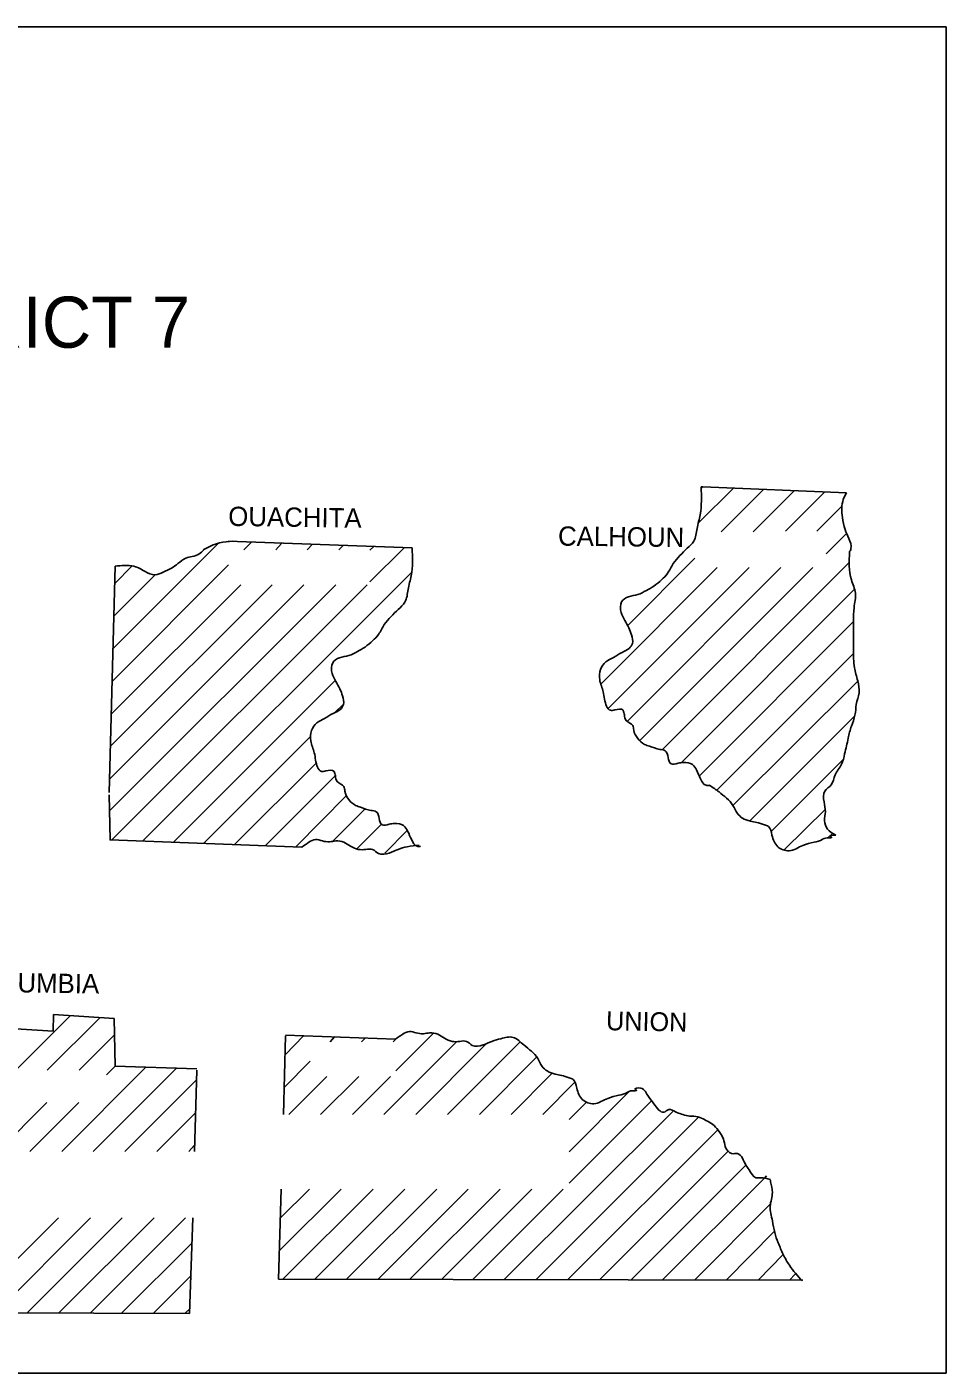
# Model space of a CAD drawing. Extents: x 21307 to 29830, y 1322443 to 1332359.
# Drawn here: x 27579.7 to 27784.6, y 1325697.4 to 1325997.4 of the extents above; entities that cross this region are included whole.
import ezdxf

# ---------------------------------------------------------------- set-up
doc = ezdxf.new("R2010")
doc.units = 0
doc.layers.add('R_Draft', color=7, linetype='Continuous')

msp = doc.modelspace()

# ---------------------------------------------------------------- linework, layer by layer
at = {"layer": 'R_Draft'}
msp.add_lwpolyline([(27384.56, 1325697.42), (27384.56, 1325997.42), (27784.56, 1325997.42), (27784.56, 1325697.42)], close=True, dxfattribs=at)
for points in [[(27729.36, 1325886.92), (27737.16, 1325894.62)], [(27762.36, 1325893.62), (27730.36, 1325894.92), (27729.96, 1325894.92)], [(27729.96, 1325894.52), (27730.36, 1325894.92)], [(27734.46, 1325884.92), (27743.96, 1325894.42)], [(27741.56, 1325884.92), (27750.76, 1325894.12)], [(27748.76, 1325885.02), (27757.56, 1325893.82)], [(27755.76, 1325885.02), (27761.26, 1325890.52)], [(27757.86, 1325880.02), (27762.36, 1325884.52)], [(27598.86, 1325858.82), (27622.46, 1325882.42)], [(27624.56, 1325882.82), (27665.56, 1325881.32)], [(27628.06, 1325880.92), (27629.76, 1325882.62)], [(27635.16, 1325880.92), (27636.46, 1325882.32)], [(27642.16, 1325880.92), (27643.36, 1325882.12)], [(27649.26, 1325880.92), (27650.16, 1325881.82)], [(27656.16, 1325880.82), (27657.06, 1325881.62)], [(27656.16, 1325873.72), (27663.76, 1325881.32)], [(27598.06, 1325826.82), (27599.36, 1325877.22)], [(27598.76, 1325851.62), (27624.66, 1325877.52)], [(27599.26, 1325873.32), (27603.16, 1325877.32)], [(27713.66, 1325864.02), (27728.56, 1325879.02)], [(27721.26, 1325836.32), (27763.06, 1325878.12)], [(27599.06, 1325866.12), (27608.26, 1325875.32)], [(27605.56, 1325816.02), (27665.46, 1325875.92)], [(27707.66, 1325851.02), (27733.56, 1325876.92)], [(27709.36, 1325845.62), (27740.66, 1325876.92)], [(27713.46, 1325842.62), (27747.76, 1325876.92)], [(27716.26, 1325838.32), (27754.86, 1325876.92)], [(27598.16, 1325822.82), (27648.56, 1325873.12)], [(27598.26, 1325829.92), (27641.46, 1325873.12)], [(27598.36, 1325837.12), (27634.36, 1325873.12)], [(27598.56, 1325844.32), (27627.36, 1325873.12)], [(27598.66, 1325816.22), (27655.56, 1325873.12)], [(27725.56, 1325833.52), (27764.06, 1325872.02)], [(27729.66, 1325830.62), (27763.96, 1325864.92)], [(27733.46, 1325827.32), (27763.86, 1325857.72)], [(27612.36, 1325815.72), (27648.46, 1325851.82)], [(27737.06, 1325823.92), (27764.86, 1325851.62)], [(27648.36, 1325844.62), (27650.16, 1325846.42)], [(27740.86, 1325820.52), (27764.26, 1325843.92)], [(27619.16, 1325815.52), (27642.86, 1325839.22)], [(27625.96, 1325815.22), (27644.26, 1325833.42)], [(27745.56, 1325818.12), (27761.46, 1325834.02)], [(27632.86, 1325815.02), (27648.46, 1325830.62)], [(27640.96, 1325814.62), (27598.26, 1325816.22), (27598.06, 1325826.32)], [(27639.66, 1325814.72), (27650.96, 1325826.12)], [(27647.96, 1325816.02), (27655.16, 1325823.22)], [(27748.46, 1325814.02), (27757.66, 1325823.12)], [(27653.26, 1325814.22), (27658.76, 1325819.72)], [(27659.46, 1325813.32), (27664.46, 1325818.32)], [(27758.36, 1325816.82), (27759.16, 1325817.62)], [(27567.56, 1325774.72), (27585.56, 1325773.62), (27585.66, 1325777.32), (27599.16, 1325776.42)], [(27577.26, 1325764.92), (27589.36, 1325777.02)], [(27584.26, 1325764.92), (27595.96, 1325776.62)], [(27599.16, 1325776.42), (27599.36, 1325765.82), (27617.56, 1325765.22)], [(27591.36, 1325764.92), (27599.16, 1325772.72)], [(27636.86, 1325755.04), (27637.36, 1325772.54)], [(27637.26, 1325768.34), (27641.46, 1325772.64)], [(27637.36, 1325772.74), (27661.86, 1325771.84)], [(27647.26, 1325771.24), (27648.36, 1325772.44)], [(27654.26, 1325771.24), (27655.16, 1325772.14)], [(27661.36, 1325771.24), (27662.26, 1325772.14)], [(27661.96, 1325764.74), (27670.36, 1325773.14)], [(27659.26, 1325755.04), (27675.46, 1325771.24)], [(27666.36, 1325755.04), (27682.16, 1325770.84)], [(27673.46, 1325755.04), (27689.56, 1325771.14)], [(27637.06, 1325761.04), (27642.86, 1325766.94)], [(27680.56, 1325755.04), (27693.26, 1325767.84)], [(27587.46, 1325746.82), (27606.16, 1325765.52)], [(27594.46, 1325746.82), (27612.96, 1325765.32)], [(27597.46, 1325763.92), (27599.36, 1325765.82)], [(27617.56, 1325764.92), (27617.06, 1325746.82)], [(27638.06, 1325755.04), (27646.56, 1325763.54)], [(27645.16, 1325755.04), (27653.66, 1325763.54)], [(27652.26, 1325755.04), (27660.76, 1325763.54)], [(27687.66, 1325755.04), (27696.76, 1325764.24)], [(27601.56, 1325746.82), (27617.46, 1325762.72)], [(27694.66, 1325755.04), (27701.86, 1325762.24)], [(27700.56, 1325746.74), (27713.96, 1325760.14)], [(27573.26, 1325746.82), (27584.16, 1325757.72)], [(27580.36, 1325746.82), (27591.26, 1325757.72)], [(27700.56, 1325739.74), (27718.86, 1325758.04)], [(27700.56, 1325753.94), (27704.26, 1325757.64)], [(27608.66, 1325746.82), (27617.26, 1325755.42)], [(27686.16, 1325718.34), (27723.66, 1325755.74)], [(27693.26, 1325718.34), (27729.36, 1325754.44)], [(27700.36, 1325718.34), (27733.66, 1325751.64)], [(27615.76, 1325746.82), (27616.96, 1325748.12)], [(27707.46, 1325718.34), (27735.96, 1325746.84)], [(27714.46, 1325718.24), (27739.96, 1325743.74)], [(27721.46, 1325718.24), (27744.06, 1325740.84), (27744.56, 1325741.34)], [(27635.76, 1325718.34), (27636.36, 1325738.44)], [(27635.96, 1325724.64), (27649.76, 1325738.44)], [(27636.16, 1325731.94), (27642.66, 1325738.44)], [(27636.76, 1325718.34), (27656.86, 1325738.44)], [(27643.86, 1325718.34), (27663.96, 1325738.44)], [(27650.96, 1325718.34), (27671.06, 1325738.44)], [(27657.96, 1325718.34), (27678.06, 1325738.44)], [(27665.06, 1325718.34), (27685.16, 1325738.44)], [(27672.16, 1325718.34), (27692.26, 1325738.44)], [(27679.16, 1325718.34), (27699.26, 1325738.44)], [(27728.46, 1325718.14), (27745.36, 1325735.04)], [(27565.66, 1325710.92), (27586.76, 1325732.02)], [(27572.76, 1325710.92), (27593.86, 1325732.02)], [(27579.76, 1325710.82), (27600.96, 1325732.02)], [(27586.86, 1325710.82), (27608.06, 1325732.02)], [(27593.86, 1325710.82), (27615.06, 1325732.02)], [(27616.66, 1325732.02), (27615.96, 1325710.72)], [(27735.56, 1325718.14), (27746.26, 1325728.94)], [(27600.86, 1325710.82), (27616.36, 1325726.32)], [(27742.66, 1325718.14), (27748.26, 1325723.84)], [(27607.96, 1325710.82), (27616.16, 1325719.02)], [(27752.66, 1325718.14), (27635.76, 1325718.34)], [(27749.66, 1325718.14), (27750.96, 1325719.44)], [(27615.96, 1325710.72), (27551.86, 1325710.92)], [(27615.06, 1325710.82), (27616.06, 1325711.82)]]:
    msp.add_lwpolyline(points, dxfattribs=at)
for points in [[(27729.96, 1325894.92), (27729.76, 1325888.72), (27729.06, 1325885.62), (27728.36, 1325882.82), (27726.86, 1325881.22), (27725.26, 1325879.62), (27723.76, 1325877.82), (27722.46, 1325875.62), (27721.16, 1325874.22), (27719.46, 1325872.82), (27717.76, 1325871.82), (27715.86, 1325870.92), (27713.76, 1325870.42), (27712.26, 1325869.32), (27712.16, 1325866.92), (27713.86, 1325863.52), (27714.46, 1325861.92), (27714.66, 1325860.02), (27713.96, 1325858.92), (27712.36, 1325858.02), (27710.46, 1325856.92), (27708.76, 1325855.92), (27707.56, 1325854.22), (27707.36, 1325851.92), (27708.16, 1325849.22), (27708.46, 1325847.62), (27709.76, 1325845.12), (27710.76, 1325845.22), (27712.56, 1325845.12), (27712.76, 1325844.62), (27712.86, 1325844.12), (27713.26, 1325842.82), (27714.76, 1325841.72), (27714.96, 1325840.72), (27715.86, 1325838.82), (27717.36, 1325837.52), (27718.46, 1325837.12), (27720.76, 1325836.42), (27721.96, 1325836.12), (27723.26, 1325833.22), (27724.86, 1325833.32), (27726.06, 1325833.52), (27728.06, 1325833.02), (27728.96, 1325831.82), (27729.86, 1325829.82), (27731.06, 1325828.42), (27731.86, 1325828.42)], [(27763.06, 1325880.42), (27763.36, 1325881.12), (27762.86, 1325883.42), (27762.06, 1325885.42), (27761.46, 1325888.12), (27761.66, 1325892.12), (27762.36, 1325893.62)], [(27599.36, 1325877.22), (27603.56, 1325877.22), (27604.86, 1325876.72), (27606.06, 1325876.02), (27608.26, 1325875.32), (27610.06, 1325875.92), (27611.96, 1325876.82), (27613.36, 1325877.82), (27615.16, 1325879.02), (27616.56, 1325879.42), (27618.06, 1325879.92), (27619.06, 1325880.82)], [(27618.96, 1325880.92), (27622.66, 1325882.42), (27625.56, 1325882.82)], [(27665.56, 1325881.32), (27665.36, 1325875.12), (27664.66, 1325872.02), (27663.96, 1325869.22), (27662.46, 1325867.62), (27660.86, 1325866.02), (27659.36, 1325864.22), (27658.06, 1325862.02), (27656.76, 1325860.62), (27655.06, 1325859.22), (27653.36, 1325858.22), (27651.46, 1325857.32), (27649.36, 1325856.82), (27647.86, 1325855.72), (27647.76, 1325853.32), (27649.46, 1325849.92), (27650.06, 1325848.32), (27650.26, 1325846.42), (27649.56, 1325845.32), (27647.96, 1325844.42), (27646.06, 1325843.32), (27644.36, 1325842.32), (27643.16, 1325840.62), (27642.96, 1325838.32), (27643.76, 1325835.62), (27644.06, 1325834.02), (27645.36, 1325831.52), (27646.36, 1325831.62), (27648.16, 1325831.52), (27648.36, 1325831.02), (27648.46, 1325830.52), (27648.86, 1325829.22), (27650.36, 1325828.12), (27650.56, 1325827.12), (27651.46, 1325825.22), (27652.96, 1325823.92), (27654.06, 1325823.52), (27656.36, 1325822.82), (27657.56, 1325822.52), (27658.86, 1325819.62), (27660.46, 1325819.72), (27661.66, 1325819.92), (27663.66, 1325819.42), (27664.56, 1325818.22), (27665.46, 1325816.22), (27666.66, 1325814.82), (27667.46, 1325814.82)], [(27759.96, 1325817.32), (27758.16, 1325818.62), (27757.46, 1325820.52), (27757.66, 1325822.52), (27757.36, 1325824.72), (27757.56, 1325827.12), (27758.96, 1325828.52), (27759.86, 1325830.72), (27761.26, 1325833.12), (27761.96, 1325835.42), (27762.76, 1325838.92), (27763.46, 1325841.62), (27764.26, 1325844.02), (27764.56, 1325846.42), (27765.16, 1325849.02), (27764.86, 1325851.72), (27764.16, 1325854.62), (27763.96, 1325856.62), (27763.96, 1325859.42), (27763.96, 1325862.12), (27763.96, 1325864.92), (27764.06, 1325868.02), (27764.36, 1325871.22), (27763.46, 1325874.22), (27763.06, 1325880.42)], [(27731.86, 1325828.42), (27733.96, 1325826.92), (27735.66, 1325825.52), (27737.06, 1325823.92), (27738.06, 1325822.12), (27739.16, 1325821.12), (27740.96, 1325820.42), (27742.36, 1325820.12), (27744.06, 1325819.62), (27744.96, 1325819.22), (27745.76, 1325817.32), (27747.06, 1325814.72), (27749.56, 1325813.82), (27752.66, 1325815.02), (27755.16, 1325815.72), (27756.96, 1325816.32), (27758.06, 1325816.72), (27759.06, 1325816.82), (27758.76, 1325817.02), (27759.96, 1325817.32)], [(27667.16, 1325815.02), (27664.46, 1325814.72), (27662.46, 1325814.12), (27660.46, 1325813.32), (27658.06, 1325813.22), (27656.76, 1325814.12), (27655.26, 1325814.12), (27653.56, 1325814.12), (27651.86, 1325814.82), (27650.36, 1325815.72), (27648.56, 1325816.02), (27647.16, 1325815.82), (27645.56, 1325816.02), (27644.06, 1325816.32), (27642.56, 1325815.72), (27640.96, 1325814.62)], [(27661.86, 1325771.84), (27663.46, 1325772.94), (27664.96, 1325773.54), (27666.46, 1325773.24), (27668.06, 1325773.04), (27669.46, 1325773.24), (27671.26, 1325772.94), (27672.76, 1325772.04), (27674.46, 1325771.34), (27676.16, 1325771.34), (27677.66, 1325771.34), (27678.96, 1325770.44), (27681.36, 1325770.54), (27683.36, 1325771.34), (27685.36, 1325771.94), (27688.06, 1325772.24), (27690.46, 1325770.54), (27692.16, 1325769.14), (27693.56, 1325767.54), (27694.56, 1325765.74), (27695.66, 1325764.74), (27697.46, 1325764.04), (27698.86, 1325763.74), (27700.56, 1325763.24), (27701.46, 1325762.84), (27702.26, 1325760.94), (27703.56, 1325758.34), (27706.06, 1325757.44), (27709.16, 1325758.64), (27711.66, 1325759.34), (27713.46, 1325759.94), (27714.56, 1325760.34), (27715.56, 1325760.44), (27715.26, 1325760.64), (27716.46, 1325760.94), (27717.56, 1325760.14), (27718.26, 1325759.04), (27719.46, 1325757.44), (27720.56, 1325756.04), (27721.66, 1325755.54), (27722.76, 1325756.14), (27724.26, 1325755.64), (27725.56, 1325755.14), (27727.06, 1325754.74), (27728.36, 1325754.64), (27730.06, 1325754.24), (27731.36, 1325753.54), (27732.56, 1325752.84), (27733.76, 1325751.54), (27734.96, 1325749.54), (27735.36, 1325747.94), (27736.76, 1325746.34), (27738.06, 1325746.34), (27739.96, 1325743.74), (27740.66, 1325742.74), (27742.16, 1325740.94), (27743.26, 1325740.94), (27745.36, 1325740.54)], [(27745.36, 1325740.54), (27745.46, 1325740.04), (27745.86, 1325737.64), (27745.36, 1325734.64), (27745.86, 1325731.34), (27746.36, 1325728.74), (27747.16, 1325726.44), (27748.26, 1325723.84), (27749.66, 1325721.44), (27752.46, 1325717.94)]]:
    msp.add_spline(points, degree=3, dxfattribs=at)

# ---------------------------------------------------------------- texts
msp.add_text('DISTRICT 7', height=11.4, dxfattribs=at).set_placement((27533.06, 1325925.92))
for s, height, rotation, p in [('OUACHITA', 4.301, 359.2043, (27624.56, 1325886.22)), ('CALHOUN', 4.301, 359.3634, (27698.06, 1325881.82)), ('COLUMBIA', 4.3, 359.2125, (27565.76, 1325782.42)), ('UNION', 4.201, 358.9584, (27708.76, 1325773.84))]:
    msp.add_text(s, height=height, rotation=rotation, dxfattribs=at).set_placement(p)

doc.saveas('drawing.dxf')
